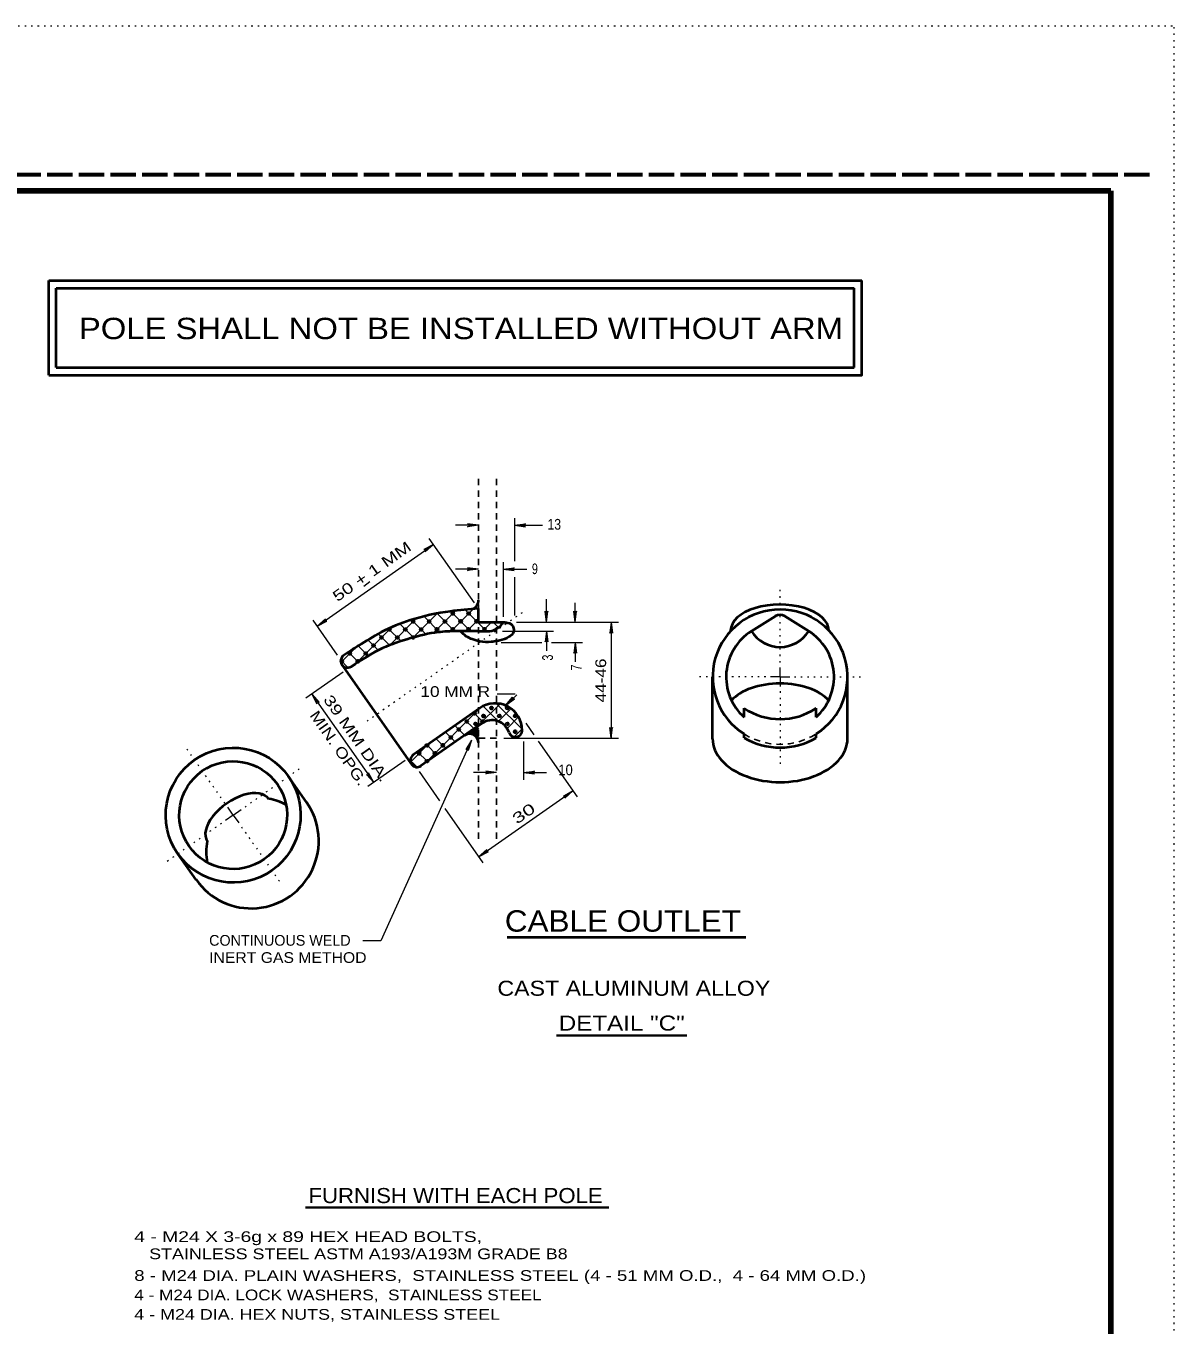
# Model space of a CAD drawing. Extents: x 312583 to 312854, y 144419 to 144597.
# Drawn here: x 312772 to 312853.5, y 144504.5 to 144596.8 of the extents above; entities that cross this region are included whole.
import ezdxf
from ezdxf.enums import TextEntityAlignment as Align

# ---------------------------------------------------------------- set-up
doc = ezdxf.new("R2010")
doc.units = 0
doc.header["$LTSCALE"] = 0.3
doc.header["$PDMODE"] = 32
doc.header["$PDSIZE"] = 0.15
for name, pattern in [('DOTTED', [1.5, 0.3, -1.2]), ('LONG_DASHED', [7.5, 6, -1.5]), ('SHORT_DASHED', [2.7, 1.5, -1.2])]:
    doc.linetypes.add(name, pattern=pattern)
for name, color, linetype, lineweight in [('1', 7, 'Continuous', 40), ('2', 7, 'Continuous', 13), ('62', 7, 'DOTTED', 13), ('63', 7, 'LONG_DASHED', 60)]:
    doc.layers.add(name, color=color, linetype=linetype, lineweight=lineweight)

msp = doc.modelspace()

# ---------------------------------------------------------------- linework, layer by layer
at = {"layer": '1', "lineweight": 158}
msp.add_line((312849, 144423.1446), (312849, 144585.0846), dxfattribs=at)
at = {"layer": '1', "linetype": 'SHORT_DASHED', "lineweight": 25}
for p, q in [((312804.0975, 144539.0569), (312804.0975, 144564.6713)), ((312805.3778, 144539.0569), (312805.3778, 144564.6713)), ((312805.3778, 144546.2023), (312804.0975, 144546.2023))]:
    msp.add_line(p, q, dxfattribs=at)
at = {"layer": '1', "linetype": 'DOTTED', "lineweight": 13}
msp.add_line((312807.1871, 144555.1186), (312796.0091, 144547.2909), dxfattribs=at)
at = {"layer": '1', "lineweight": 13}
for p, q in [((312799.4285, 144553.3323), (312801.1075, 144555.0189)), ((312801.3375, 144553.7463), (312800.2335, 144554.8503)), ((312800.9005, 144553.6849), (312802.4645, 144555.2489)), ((312802.3878, 144553.8153), (312801.1765, 144555.0343)), ((312802.1271, 144553.7923), (312803.7065, 144555.3716)), ((312803.4995, 144553.8383), (312802.1348, 144555.2029)), ((312804.6341, 144553.8229), (312803.1391, 144555.3256)), ((312795.3498, 144551.4999), (312797.9488, 144554.0989)), ((312798.5928, 144553.1023), (312797.7111, 144553.9839)), ((312797.8338, 144552.8569), (312799.6508, 144554.6816)), ((312799.4745, 144553.3476), (312798.4778, 144554.3443)), ((312800.3868, 144553.5623), (312799.3518, 144554.5973)), ((312803.2848, 144553.8383), (312804.0898, 144554.6433)), ((312804.3965, 144553.8229), (312805.0175, 144554.4516)), ((312805.4698, 144554.1219), (312805.1401, 144554.4516)), ((312796.9751, 144552.4659), (312796.2468, 144553.1943)), ((312797.7418, 144552.8263), (312796.9598, 144553.6083)), ((312794.3531, 144551.6303), (312795.4111, 144552.6806)), ((312795.5568, 144551.6303), (312794.8668, 144552.3203)), ((312796.2545, 144552.0596), (312795.5491, 144552.7649)), ((312794.7978, 144551.2623), (312794.3455, 144551.7146)), ((312800.3255, 144544.4619), (312804.2431, 144548.3796)), ((312804.0591, 144547.0763), (312805.6385, 144548.6479)), ((312805.5158, 144547.3983), (312804.4118, 144548.4946)), ((312807.2025, 144546.8463), (312805.3471, 144548.6786)), ((312803.7831, 144546.8769), (312803.0855, 144547.5669)), ((312804.4348, 144547.3446), (312803.7525, 144548.0269)), ((312805.5005, 144547.3983), (312806.4128, 144548.3106)), ((312806.1291, 144546.8999), (312806.9418, 144547.7203)), ((312802.4491, 144545.9416), (312801.7591, 144546.6393)), ((312803.1161, 144546.4093), (312802.4261, 144547.0993)), ((312806.6351, 144546.2943), (312807.2025, 144546.8616)), ((312799.3518, 144544.6076), (312800.5018, 144545.7576)), ((312801.1305, 144545.0139), (312800.4405, 144545.7039)), ((312801.7898, 144545.4816), (312801.0998, 144546.1716)), ((312800.4635, 144544.5539), (312799.7735, 144545.2439)), ((312799.6891, 144544.1936), (312799.3748, 144544.5156))]:
    msp.add_line(p, q, dxfattribs=at)
at = {"layer": '1'}
for p, q in [((312804.0975, 144554.4516), (312804.0975, 144555.4099)), ((312825.1808, 144554.8733), (312823.4865, 144553.8076)), ((312825.8555, 144554.8733), (312827.5498, 144553.8076)), ((312804.0975, 144554.4516), (312805.8531, 144554.4516)), ((312804.0975, 144553.8076), (312804.8948, 144553.8076)), ((312799.3135, 144544.4083), (312794.4758, 144551.3313)), ((312820.7265, 144546.1716), (312820.7265, 144550.5569)), ((312830.3098, 144546.1716), (312830.3098, 144550.5569)), ((312804.1818, 144548.3336), (312799.4591, 144545.0293)), ((312822.9651, 144547.7049), (312822.9651, 144548.3336)), ((312828.0711, 144547.7049), (312828.0711, 144548.3336)), ((312804.3198, 144547.2526), (312800.0111, 144544.2396)), ((312803.0931, 144546.4016), (312804.3198, 144547.2526)), ((312803.4765, 144546.5089), (312804.0975, 144546.9459)), ((312803.6451, 144546.4859), (312804.0975, 144546.8003)), ((312803.7755, 144546.4323), (312804.0975, 144546.6546)), ((312803.8828, 144546.3556), (312804.0975, 144546.5013)), ((312822.9651, 144546.2406), (312822.9651, 144546.5089)), ((312828.0711, 144546.2406), (312828.0711, 144546.5089)), ((312803.9671, 144546.2636), (312804.0975, 144546.3556)), ((312804.0285, 144546.1563), (312804.0975, 144546.2023)), ((312791.8845, 144541.6636), (312790.5965, 144543.4959)), ((312784.0338, 144536.1589), (312782.7458, 144537.9913))]:
    msp.add_line(p, q, dxfattribs=at)
at = {"layer": '1', "lineweight": 158}
msp.add_lwpolyline([(312616.5, 144423.1446), (312616.5, 144585.0846), (312849, 144585.0846)], dxfattribs=at)
at = {"layer": '1'}
for centre, radius, start, end in [((312803.4586, 144556.0003), 0.6389, 274.52387, 0), ((312825.5181, 144550.5595), 4.7891, 302.26476, 237.73524), ((312825.5181, 144554.3292), 0.6389, 57.96874, 122.03126), ((312804.7321, 144555.0969), 1.297, 277.20711, 330.03225), ((312825.5181, 144550.5595), 3.8333, 122.03776, 228.18882), ((312825.5181, 144555.0828), 2.3995, 212.03126, 327.96874), ((312825.5181, 144550.5595), 3.8333, 311.81031, 57.96224), ((312794.79, 144551.696), 0.4807, 125.00164, 305.00164), ((312805.2832, 144546.764), 1.9167, 0, 125.01416), ((312825.5181, 144552.1813), 4.6169, 236.39125, 303.60875), ((312805.0507, 144546.2083), 1.2778, 18.24978, 124.99202), ((312803.4586, 144545.8746), 0.6389, 0, 125.00321), ((312806.7195, 144546.7619), 0.4804, 198.353, 0), ((312825.5181, 144550.5595), 5.0168, 239.38652, 300.62404), ((312799.7377, 144544.6357), 0.4807, 125.04193, 305.04193)]:
    msp.add_arc(centre, radius, start, end, dxfattribs=at)
at = {"layer": '1', "linetype": 'SHORT_DASHED', "lineweight": 25}
msp.add_arc((312825.5181, 144550.5595), 4.7891, 237.73524, 302.26476, dxfattribs=at)
at = {"layer": '1'}
for centre, major_axis, ratio, start_param, end_param in [((312825.49, 144553.8613), (3.4832, 0.0051), 0.5283, 6.2831853, 9.424778), ((312825.5181, 144547.963), (-3.8308, 0), 0.555704, 3.5912894, 5.8336047), ((312825.5181, 144546.1742), (-4.7891, 0), 0.64461, 6.2831853, 9.424778), ((312787.0161, 144540.4063), (-2.1824, -1.5001), 0.537251, 3.1255912, 6.2961342), ((312788.5852, 144538.1216), (-3.1362, -2.1981), 0.999836, 3.598371, 3.9338982), ((312787.9566, 144538.9138), (-3.9233, -2.7501), 0.999869, 0.0001305, 3.1417232), ((312788.5852, 144538.1216), (-3.1362, -2.1981), 0.999836, 5.4703118, 5.8646097)]:
    msp.add_ellipse(centre, major_axis=major_axis, ratio=ratio, start_param=start_param, end_param=end_param, dxfattribs=at)
for major_axis, ratio in [((-3.9233, -2.7501), 0.999869), ((-3.1362, -2.1981), 0.999836)]:
    msp.add_ellipse((312786.6737, 144540.7436), major_axis=major_axis, ratio=ratio, dxfattribs=at)
for points in [[(312804.0975, 144555.4099), (312802.0811, 144555.2106), (312799.2445, 144554.5819), (312797.1745, 144553.7309), (312795.5798, 144552.7803), (312794.5141, 144552.0903)], [(312805.8531, 144554.4516), (312806.2901, 144554.3749), (312806.4588, 144554.2676), (312806.5891, 144553.7616), (312806.2518, 144553.4013), (312805.6231, 144553.1483), (312805.2091, 144553.0716), (312805.0021, 144553.0409), (312804.2125, 144553.0793), (312803.6528, 144553.2326), (312803.2311, 144553.4396), (312802.8325, 144553.7923)], [(312804.0975, 144553.8076), (312802.5258, 144553.8076), (312801.2225, 144553.7309), (312799.2598, 144553.3016), (312797.2818, 144552.5963), (312795.0661, 144551.3006)]]:
    msp.add_spline(points, degree=3, dxfattribs=at)
for p in [(312802.2728, 144555.0649), (312803.3998, 144555.0649), (312797.7725, 144553.9226), (312798.8995, 144553.9303), (312799.4591, 144554.4899), (312800.0188, 144553.9303), (312800.5861, 144554.4976), (312801.1458, 144553.9379), (312801.7131, 144554.4976), (312802.2651, 144553.9379), (312802.8325, 144554.5053), (312803.3921, 144553.9456), (312803.9518, 144554.5053), (312804.5191, 144553.9456), (312797.2051, 144553.3629), (312798.3321, 144553.3629), (312799.4591, 144553.3629), (312794.9588, 144552.2283), (312796.0858, 144552.2283), (312796.6455, 144552.7956), (312794.3915, 144551.6609), (312795.5185, 144551.6686), (312805.0251, 144548.3489), (312806.1445, 144548.3489), (312803.2618, 144547.3983), (312803.8215, 144547.9579), (312804.3811, 144547.3983), (312804.4578, 144547.7816), (312805.5771, 144547.7893), (312806.7041, 144547.7893), (312802.6945, 144546.8309), (312803.8905, 144547.2219), (312806.1445, 144547.2296), (312806.7041, 144546.6699), (312800.4405, 144545.6963), (312801.5675, 144545.7039), (312802.1271, 144546.2636), (312799.8808, 144545.1366), (312800.4405, 144544.5769), (312801.0078, 144545.1366)]:
    msp.add_point(p, dxfattribs=at)
at = {"layer": '2', "lineweight": 40}
for p, q in [((312773.5684, 144578.7003), (312831.3273, 144578.7003)), ((312773.5684, 144571.9825), (312773.5684, 144578.7003)), ((312774.1073, 144578.1613), (312830.7816, 144578.1613)), ((312774.1073, 144572.5215), (312774.1073, 144578.1613)), ((312830.7816, 144572.5215), (312830.7816, 144578.1613)), ((312774.1073, 144572.5215), (312830.7816, 144572.5215)), ((312806.1308, 144532.0803), (312823.0861, 144532.0803))]:
    msp.add_line(p, q, dxfattribs=at)
at = {"layer": '2'}
for p, q in [((312804.0975, 144561.3286), (312802.4645, 144561.3286)), ((312803.3231, 144561.4283), (312803.5685, 144561.3286)), ((312804.0975, 144561.3286), (312803.3231, 144561.4283)), ((312803.3231, 144561.2289), (312803.5685, 144561.3286)), ((312804.0975, 144561.3286), (312803.3231, 144561.2289)), ((312806.6505, 144561.8423), (312806.6505, 144558.7756)), ((312806.6505, 144561.3286), (312807.4248, 144561.4283)), ((312806.6505, 144561.3286), (312808.6515, 144561.3286)), ((312806.6505, 144561.3286), (312807.4248, 144561.2289)), ((312807.4248, 144561.4283), (312807.1795, 144561.3286)), ((312807.4248, 144561.2289), (312807.1795, 144561.3286)), ((312803.8138, 144555.8163), (312800.5938, 144560.3856)), ((312792.6358, 144554.1603), (312800.8928, 144559.9716)), ((312800.8928, 144559.9716), (312800.2105, 144559.6036)), ((312800.2105, 144559.6036), (312800.4635, 144559.6649)), ((312800.8928, 144559.9716), (312800.3178, 144559.4503)), ((312800.3178, 144559.4503), (312800.4635, 144559.6649)), ((312805.8531, 144558.7143), (312805.8531, 144554.8349)), ((312804.0975, 144558.2083), (312802.4645, 144558.2083)), ((312803.3231, 144558.3003), (312803.5685, 144558.2083)), ((312804.0975, 144558.2083), (312803.3231, 144558.3003)), ((312803.3231, 144558.1086), (312803.5685, 144558.2083)), ((312804.0975, 144558.2083), (312803.3231, 144558.1086)), ((312805.8531, 144558.2083), (312806.6275, 144558.3003)), ((312805.8531, 144558.2083), (312807.5176, 144558.2083)), ((312805.8531, 144558.2083), (312806.6275, 144558.1086)), ((312806.6275, 144558.3003), (312806.3821, 144558.2083)), ((312806.6275, 144558.1086), (312806.3821, 144558.2083)), ((312806.6505, 144557.6333), (312806.6505, 144554.9269)), ((312796.3705, 144557.3128), (312795.9488, 144556.9832)), ((312808.9198, 144554.4516), (312808.9198, 144556.0769)), ((312810.9668, 144554.4516), (312810.9668, 144555.8152)), ((312808.8278, 144555.2183), (312808.9198, 144554.9729)), ((312808.9198, 144554.4516), (312808.8278, 144555.2183)), ((312809.0195, 144555.2183), (312808.9198, 144554.9729)), ((312808.9198, 144554.4516), (312809.0195, 144555.2183)), ((312810.8671, 144555.2183), (312810.9668, 144554.9729)), ((312810.9668, 144554.4516), (312810.8671, 144555.2183)), ((312811.0665, 144555.2183), (312810.9668, 144554.9729)), ((312810.9668, 144554.4516), (312811.0665, 144555.2183)), ((312794.0848, 144552.1056), (312792.3445, 144554.5819)), ((312792.6358, 144554.1603), (312793.2185, 144554.6816)), ((312792.6358, 144554.1603), (312793.3258, 144554.5283)), ((312793.2185, 144554.6816), (312793.0651, 144554.4669)), ((312793.3258, 144554.5283), (312793.0651, 144554.4669)), ((312806.7885, 144554.4516), (312814.0335, 144554.4516)), ((312813.5198, 144554.4516), (312813.4278, 144553.6773)), ((312813.4278, 144553.6773), (312813.5198, 144553.9226)), ((312813.5198, 144554.4516), (312813.5198, 144546.2023)), ((312813.5198, 144554.4516), (312813.6195, 144553.6773)), ((312813.6195, 144553.6773), (312813.5198, 144553.9226)), ((312805.6998, 144553.0103), (312808.5901, 144553.0103)), ((312805.7918, 144553.8076), (312809.4335, 144553.8076)), ((312808.9198, 144553.8153), (312808.8278, 144553.0409)), ((312808.8278, 144553.0409), (312808.9198, 144553.2863)), ((312808.9198, 144553.8153), (312808.9198, 144552.4109)), ((312808.9198, 144553.8153), (312809.0195, 144553.0409)), ((312809.0195, 144553.0409), (312808.9198, 144553.2863)), ((312809.2801, 144553.0103), (312811.4805, 144553.0103)), ((312810.9668, 144553.0103), (312810.8671, 144552.2359)), ((312810.9668, 144553.0103), (312810.9668, 144551.6307)), ((312810.9668, 144553.0103), (312811.0665, 144552.2359)), ((312810.8671, 144552.2359), (312810.9668, 144552.4813)), ((312811.0665, 144552.2359), (312810.9668, 144552.4813)), ((312825.5181, 144550.5569), (312825.5181, 144551.2393)), ((312825.5181, 144550.5569), (312825.5181, 144551.2393)), ((312794.4911, 144550.9019), (312791.8385, 144549.0389)), ((312825.5181, 144550.5569), (312824.8358, 144550.5569)), ((312825.5181, 144550.5569), (312826.2005, 144550.5569)), ((312825.5181, 144550.5569), (312825.5181, 144549.8823)), ((312792.2525, 144549.3303), (312796.6531, 144543.0589)), ((312792.2525, 144549.3303), (312792.6205, 144548.6403)), ((312792.2525, 144549.3303), (312792.7738, 144548.7476)), ((312805.4238, 144549.3533), (312806.7041, 144549.3533)), ((312806.0141, 144548.5329), (312806.8268, 144549.2919)), ((312792.6205, 144548.6403), (312792.5591, 144548.9009)), ((312792.7738, 144548.7476), (312792.5591, 144548.9009)), ((312806.0141, 144548.5329), (312806.5125, 144549.1309)), ((312806.0141, 144548.5329), (312806.6428, 144548.9929)), ((312806.5125, 144549.1309), (312806.3975, 144548.8933)), ((312806.6428, 144548.9929), (312806.3975, 144548.8933)), ((312807.4631, 144547.2679), (312808.0305, 144546.4476)), ((312813.4278, 144546.9689), (312813.5198, 144546.7236)), ((312813.5198, 144546.2023), (312813.4278, 144546.9689)), ((312813.6195, 144546.9689), (312813.5198, 144546.7236)), ((312813.5198, 144546.2023), (312813.6195, 144546.9689)), ((312803.5991, 144546.0719), (312797.1515, 144531.8196)), ((312803.5991, 144546.0719), (312803.2005, 144545.4049)), ((312803.2005, 144545.4049), (312803.3845, 144545.5889)), ((312803.5991, 144546.0719), (312803.3691, 144545.3283)), ((312803.3691, 144545.3283), (312803.3845, 144545.5889)), ((312805.8838, 144546.2023), (312814.0335, 144546.2023)), ((312807.2945, 144545.9799), (312807.2945, 144543.2583)), ((312808.3448, 144545.9953), (312811.0971, 144542.0469)), ((312798.8918, 144544.6306), (312796.2391, 144542.7676)), ((312796.2928, 144543.7413), (312796.3541, 144543.4883)), ((312796.6531, 144543.0589), (312796.2928, 144543.7413)), ((312799.8808, 144543.8333), (312801.3298, 144541.7556)), ((312805.3855, 144543.7719), (312803.7525, 144543.7719)), ((312804.6111, 144543.8716), (312804.8565, 144543.7719)), ((312805.3855, 144543.7719), (312804.6111, 144543.8716)), ((312804.6111, 144543.6723), (312804.8565, 144543.7719)), ((312805.3855, 144543.7719), (312804.6111, 144543.6723)), ((312807.2945, 144543.7719), (312808.0688, 144543.8716)), ((312807.2945, 144543.7719), (312808.9275, 144543.7719)), ((312807.2945, 144543.7719), (312808.0688, 144543.6723)), ((312808.0688, 144543.8716), (312807.8235, 144543.7719)), ((312808.0688, 144543.6723), (312807.8235, 144543.7719)), ((312796.1318, 144543.6339), (312796.3541, 144543.4883)), ((312796.6531, 144543.0589), (312796.1318, 144543.6339)), ((312804.1051, 144537.7843), (312810.8058, 144542.4609)), ((312810.8058, 144542.4609), (312810.1235, 144542.1006)), ((312810.1235, 144542.1006), (312810.3765, 144542.1619)), ((312810.8058, 144542.4609), (312810.2308, 144541.9396)), ((312810.2308, 144541.9396), (312810.3765, 144542.1619)), ((312786.6711, 144540.7436), (312786.2878, 144541.3033)), ((312786.6711, 144540.7436), (312786.2878, 144541.3033)), ((312786.6711, 144540.7436), (312787.2308, 144541.1346)), ((312801.6978, 144541.2113), (312804.3965, 144537.3626)), ((312786.6711, 144540.7436), (312786.1191, 144540.3603)), ((312786.6711, 144540.7436), (312787.0621, 144540.1916)), ((312804.1051, 144537.7843), (312804.6801, 144538.2979)), ((312804.6801, 144538.2979), (312804.5345, 144538.0756)), ((312804.1051, 144537.7843), (312804.7875, 144538.1446)), ((312804.7875, 144538.1446), (312804.5345, 144538.0756)), ((312797.1515, 144531.8196), (312795.8711, 144531.8196))]:
    msp.add_line(p, q, dxfattribs=at)
at = {"layer": '2', "linetype": 'DOTTED'}
for p, q in [((312825.5181, 144551.5843), (312825.5181, 144557.0123)), ((312824.4985, 144550.5569), (312819.5381, 144550.5569)), ((312826.5378, 144550.5569), (312831.4368, 144550.5569)), ((312825.5181, 144549.5373), (312825.5181, 144544.1399)), ((312786.0885, 144541.5869), (312783.2825, 144545.5889)), ((312787.5145, 144541.3339), (312791.5318, 144544.1476)), ((312785.8355, 144540.1609), (312781.7491, 144537.2936)), ((312787.2615, 144539.9079), (312790.0368, 144535.9366))]:
    msp.add_line(p, q, dxfattribs=at)
at = {"layer": '2', "lineweight": 35}
for p, q in [((312809.6348, 144525.1036), (312818.8832, 144525.1036)), ((312791.819, 144512.8852), (312813.347, 144512.8852))]:
    msp.add_line(p, q, dxfattribs=at)
at = {"layer": '2', "lineweight": 40}
msp.add_lwpolyline([(312773.5684, 144571.9825), (312831.3273, 144571.9825), (312831.3273, 144578.7003)], dxfattribs=at)
at = {"layer": '62'}
msp.add_line((312601.2, 144596.7846), (312853.5, 144596.7846), dxfattribs=at)
msp.add_lwpolyline([(312601.2, 144418.5846), (312853.5, 144418.5846), (312853.5, 144596.7846)], dxfattribs=at)
at = {"layer": '63'}
msp.add_line((312851.75, 144586.2246), (312583.526, 144586.2246), dxfattribs=at)

# ---------------------------------------------------------------- texts
at = {"layer": '2'}
for s, height, width, p in [('POLE SHALL NOT BE INSTALLED WITHOUT ARM', 1.516, 1.15, (312802.8494, 144574.5461)), ('CABLE OUTLET', 1.52, 1.1, (312814.3512, 144532.4685)), ('CAST ALUMINUM ALLOY', 1.07, 1.15, (312815.1316, 144527.9156)), ('DETAIL "C"', 1.07, 1.2, (312814.2691, 144525.443)), ('FURNISH WITH EACH POLE', 1.07, 1.1, (312802.4687, 144513.1938))]:
    msp.add_text(s, height=height, dxfattribs=dict(at, width=width)).set_placement(p, align=Align.CENTER)
for s, width, p in [('13', 0.85, (312808.9994, 144561.0181)), ('9', 0.75, (312807.8885, 144557.8564)), ('10 MM R', 1.2, (312799.9722, 144549.1395)), ('10', 0.9, (312809.7718, 144543.5798)), ('INERT GAS METHOD', 1.1, (312784.963, 144530.2513)), ('4 - M24 X 3-6g x 89 HEX HEAD BOLTS,  ', 1.35, (312779.6443, 144510.4308)), ('   STAINLESS STEEL ASTM A193/A193M GRADE B8', 1.25, (312779.6443, 144509.2108)), ('8 - M24 DIA. PLAIN WASHERS,  STAINLESS STEEL (4 - 51 MM O.D.,  4 - 64 MM O.D.)', 1.3, (312779.6443, 144507.6708)), ('4 - M24 DIA. LOCK WASHERS,  STAINLESS STEEL', 1.2, (312779.6443, 144506.2908)), ('4 - M24 DIA. HEX NUTS, STAINLESS STEEL', 1.25, (312779.6443, 144504.9108))]:
    msp.add_text(s, height=0.76, dxfattribs=dict(at, width=width)).set_placement(p)
for s, rotation, width, p in [('50 + 1 MM', 35.155, 1.35, (312794.0744, 144555.8608)), ('3', 90, 0.75, (312809.381, 144551.7211)), ('7', 90, 0.75, (312811.4152, 144551.0146)), ('44-46', 90, 1.2, (312813.1606, 144548.748)), ('39 MM DIA.', 305.046, 1.35, (312793.0354, 144548.9492)), ('MIN. OPG.', 305.059, 1.25, (312792.0656, 144547.83)), ('30', 34.843, 1.5, (312806.8261, 144540.0646))]:
    msp.add_text(s, height=0.76, rotation=rotation, dxfattribs=dict(at, width=width)).set_placement(p)
msp.add_text('CONTINUOUS WELD', height=0.76, dxfattribs=at).set_placement((312784.963, 144531.4713))

doc.saveas('drawing.dxf')
